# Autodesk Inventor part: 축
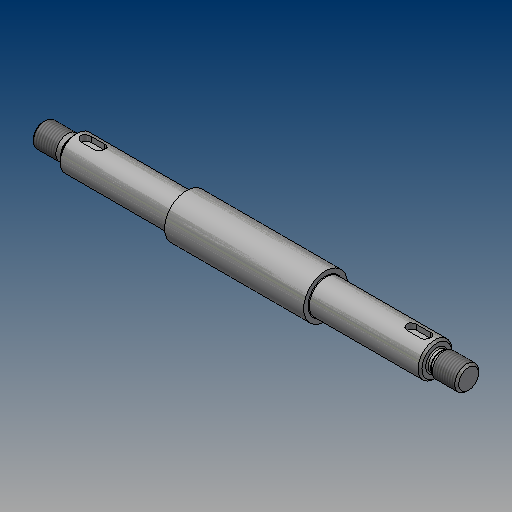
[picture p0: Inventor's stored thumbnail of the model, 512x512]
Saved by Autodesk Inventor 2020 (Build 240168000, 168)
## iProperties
Created: 2018-11
Part Number: 축
Material: 강철, 연강
Document SubType Name: Modeling
Designer: mduedu
Density: 1 g/cm^3
Appearance: 강철
Author: mduedu
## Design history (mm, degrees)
sketch "스케치1"
  geometry: L1 (-35, 0)-(35, 0); L2 (35, 0)-(35, 11); L3 (35, 11)-(-35, 11); L4 (-35, 11)-(-35, 0); L5 (-35, 0)-(-91, 0); L6 (-91, 0)-(-91, 7.5); L7 (-91, 8.5)-(-90, 8.5); L8 (-35, 8.5)-(-35, 0); L9 (-91, 0)-(-107, 0); L10 (-107, 0)-(-107, 6); L11 (-107, 6)-(-94.732, 6); L12 (-91, 5)-(-91, 0); L13 (0, 0)-(0, 11); L14 (35, 0)-(91, 0); L15 (91, 0)-(91, 5); L16 (91, 8.5)-(90, 8.5); L17 (35, 8.5)-(35, 0); L18 (91, 0)-(107, 0); L19 (107, 0)-(107, 6); L20 (107, 6)-(94.732, 6); L21 (-91, 7.5)-(-90, 8.5); L22 (-90, 8.5)-(-35, 8.5); L23 (-91, 7.5)-(-91, 8.5); L24 (91, 7.5)-(90, 8.5); L25 (91, 7.5)-(91, 8.5); L26 (90, 8.5)-(35, 8.5); L27 (91, 5)-(91, 7.5); L28 (-94.732, 6)-(-93, 5); L29 (-93, 5)-(-91, 5); L30 (94.732, 6)-(93, 5); L31 (93, 5)-(91, 5); 1 further point
  constraints: 62 end point, 8 parallel, 8 symmetric about line, 5 perpendicular, 3 horizontal, 2 collinear, 2 midpoint, 2 vertical, 1 coincident
  dimensions: "d0" = 22 diameter of L3 L1; "d2" = 17 diameter of L7 L5; "d3" = 12 diameter of L11 L9; "d4" = 70 distance of L2.end L3.end; "d5" = 56 distance of L7.start L8.start; "d6" = 214 distance between parallel lines of L19 L10; "d26" = 45 deg angle of L22 L21; "d30" = 45 deg angle of L16 L24 (= d26); "d32" = 30 deg angle of L11 L28; "d33" = 10 diameter of L29 L9 (computed from d3); "d34" = 2 distance of L12.start L28.end; "d37" = 1 horizontal distance of L6.end L7.end
revolve "회전1" sketch "스케치1" stored, may be unused: angle "d7" = 90 deg
fillet "모깎기1" dims "d8" = 0.3
node "작업 평면1"
sketch "스케치2" dims "d11" = 12
  geometry: L1 (78.5, 2.5)-(85.5, 2.5); L2 (85.5, 2.5)-(85.5, -2.5); L3 (85.5, -2.5)-(78.5, -2.5); L4 (78.5, -2.5)-(78.5, 2.5); L5 (91, 7.5)-(91, -7.5) reference; 3 further points
  constraints: 8 end point, 2 midpoint, 2 parallel, 2 vertical alignment, 1 horizontal, 1 horizontal alignment, 1 perpendicular, 4 other
  dimensions: "d10" = 5 distance between parallel lines of L3 L1; "d28" = 3 dimension on L5
extrude "돌출1" cut sketch "스케치2" distance "d12" = 3; taper "d13" = 0 deg
feature "스레드1" dims "d17" = 12, "d18" = 0
feature "스레드2" dims "d19" = 12, "d20" = 0
chamfer "모따기2" distance "d21" = 1; stored, may be unused: second distance "d22" = 2, angle "d23" = 45 deg
fillet "모깎기2" dims "d35" = 0.6
node "솔리드1"
mirror "대칭1"
other parameters: "d27" = 8.5
